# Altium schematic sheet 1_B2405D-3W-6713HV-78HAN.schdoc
size 289 x 200 mm; Name: default297x210; Symbol: default297x210; Device: default297x210; Date: 2025.06.12; Rev: V1.1; Size: "A4"; Id: /; File: B2405D-3W-6713HV-78HAN; Sheet: /; @Page No: 1; @Page Count: 1; @Schematic Name: B2405D-3W-6713HV-78HAN; @Project Name: B2405D-3W-6713HV-78HAN; @Board Name: B2405D-3W-6713HV-78HAN; @Update Date: 2025-06-12; @Create Time: 15:32:33; @Update Time: 16:55:20; @Page Name: B2405D-3W-6713HV-78HAN; @Create Date: 2025-06-12
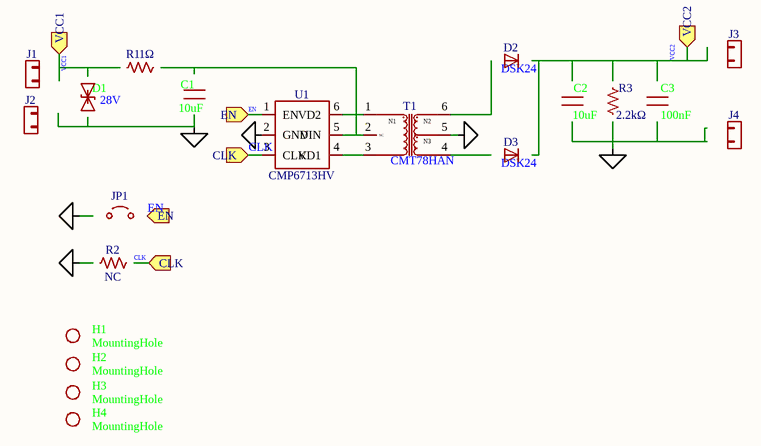
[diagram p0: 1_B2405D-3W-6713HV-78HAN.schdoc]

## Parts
C1  10uF  [C0805]
C2  10uF  [C0805]
C3  100nF  [C0603]
D1  Reverse Stand-Off Voltage (Vrwm): 28V  [SOD-123FL_L2.8-W1.8-LS3.7-BI]  (hidden comment: SMF28CA)
D2  DSK24  [SOD-123_L2.8-W1.8-LS3.7-RD]
D3  DSK24  [SOD-123_L2.8-W1.8-LS3.7-RD]
H1  value MountingHole  [MountingHole:MountingHole_3.2mm_M3]  (hidden comment: Mechanical_MountingHole)
H2  value MountingHole  [MountingHole:MountingHole_3.2mm_M3]  (hidden comment: Mechanical_MountingHole)
H3  value MountingHole  [MountingHole:MountingHole_3.2mm_M3]  (hidden comment: Mechanical_MountingHole)
H4  value MountingHole  [MountingHole:MountingHole_3.2mm_M3]  (hidden comment: Mechanical_MountingHole)
J1  Connector_Generic_Conn_01x02  [Connector_PinHeader_2.54mm:PinHeader_1x02_P2.54mm_Vertical]  (value not drawn)
J2  Connector_Generic_Conn_01x02  [Connector_PinHeader_2.54mm:PinHeader_1x02_P2.54mm_Vertical]  (value not drawn)
J3  Connector_Generic_Conn_01x02  [Connector_PinHeader_2.54mm:PinHeader_1x02_P2.54mm_Vertical]  (value not drawn)
J4  Connector_Generic_Conn_01x02  [Connector_PinHeader_2.54mm:PinHeader_1x02_P2.54mm_Vertical]  (value not drawn)
JP1  Jumper_Jumper_2_Open  [Connector_PinHeader_2.54mm:PinHeader_1x02_P2.54mm_Vertical]  (value not drawn)
R1  1Ω  [R0603]
R2  NC  [R0603]
R3  2.2kΩ  [R0603]
T1  CMT78HAN  [SMD-6_L9.7-W8.9-P2.54-LS12.8-TL]
U1  CMP6713HV  [Package_TO_SOT_SMD:TSOT-23-6]

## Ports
CLK (in), EN (in), VCC1 (in), VCC2 (in)

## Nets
GND1: U1.2(GND)
GND2: T1.5
CLK: U1.3(CLK) ; port CLK
EN: U1.1(EN) ; port EN
NetT1_1: T1.1 U1.6(VD2)
NetT1_2: T1.2 U1.5(VIN)
NetT1_3: T1.3 U1.4(VD1)

Not connected (* = marked no-connect by the designer): T1 4 6

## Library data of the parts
C1 = CGA0805X5R106K350MT: Manufacturer: HRE(芯声); Symbol: My_Library_C; Add into BOM: yes; Tolerance: ±10%; Voltage Rating: 35V; Temperature Coefficient: X5R
C2 = CC0805KKX5R6BB106: Manufacturer: YAGEO(国巨); Symbol: My_Library_C; Add into BOM: yes; Tolerance: ±10%; Voltage Rated: 10V; Temperature Coefficient: X5R
C3 = CC0603KRX7R9BB104: Manufacturer: YAGEO(国巨); Symbol: My_Library_C; Add into BOM: yes; Tolerance: ±10%; Voltage Rating: 50V; Temperature Coefficient: X7R
D1 = SMF28CA_C364280: Manufacturer: MDD(辰达半导体); Symbol: Diode_SMAJ30CA; Add into BOM: yes; polarity: 双向; Maximum Clamping Voltage: 45.4V; Peak Pulse Current (Ipp): 4.4A; Peak Pulse Power Dissipation (Ppp): 200W; Breakdown Voltage: 34.4V; Reverse Leakage Current (Ir): 1uA; Type: TVS
D2 D3 = DSK24 K24: Manufacturer: MDD(辰达半导体); Symbol: My_Library_D; Add into BOM: yes; Diode Configuration: 独立式; Forward Voltage (Vf@If): 550mV@2A; Reverse Voltage (Vr): 40V; Rectified Current: 2A; Reverse Leakage Current (Ir): 500uA@40V
H1-H4 = Mechanical_MountingHole: Users: REF**; ki_fp_filters: MountingHole*; Add into BOM: yes
J1-J4 = Connector_Generic_Conn_01x02: Users: REF**; ki_fp_filters: Jumper* TestPoint*2Pads* TestPoint*Bridge*; Add into BOM: yes
JP1 = Jumper_Jumper_2_Open: Add into BOM: yes
R1 = RC0603FR-071RL: Manufacturer: YAGEO(国巨); Symbol: My_Library_R; Add into BOM: yes; Tolerance: ±1%; Power(Watts): 100mW; Overload Voltage (Max): 75V; Temperature Coefficient: ±200ppm/℃
R2 = RC0603FR-0715KL: Symbol: My_Library_R; Add into BOM: yes; Tolerance: ±1%
R3 = RC0603FR-072K2L: Manufacturer: YAGEO(国巨); Symbol: My_Library_R; Add into BOM: yes; Tolerance: ±1%; Power(Watts): 100mW; Voltage-Supply(Max): 75V; Temperature Coefficient: ±100ppm/℃
T1 = CMT78G5N: Manufacturer: coileasy(线易); Symbol: My_Library_VPT85BB-02A; Add into BOM: yes
U1 = MYLibrary_CMP6713RE/HV: Users: REF**; Value: ~; Add into BOM: yes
